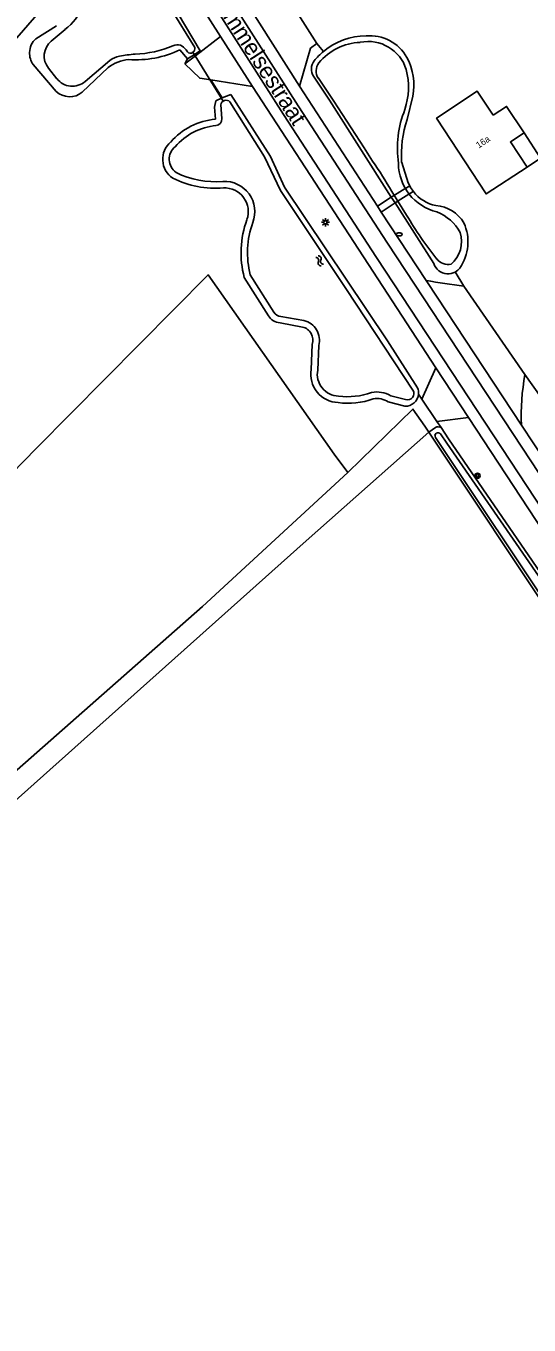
# Model space of a CAD drawing. Extents: x 137000 to 140001, y 403500 to 406000.
# Drawn here: x 139647.6 to 139724.5, y 403500 to 403698.8 of the extents above; entities that cross this region are included whole.
import ezdxf

# ---------------------------------------------------------------- set-up
doc = ezdxf.new("R2010")
doc.units = 0
for name, color, linetype in [('gg-afsc-erfafscheiding', 7, 'Continuous'), ('gg-anno-huisnummerreeks BGT', 7, 'Continuous'), ('gg-anno-openbare ruimte label', 7, 'Continuous'), ('gg-bbg-hoofdgebouw', 7, 'Continuous'), ('gg-bbg-luifel en loopbrug', 7, 'Continuous'), ('gg-knt-bronhoudergrens', 7, 'Continuous'), ('gg-knt-verharding', 7, 'Continuous'), ('gg-knt-verharding nz', 7, 'Continuous'), ('gg-kntw-bovenkant insteek waterloop', 7, 'Continuous'), ('gg-kntw-waterlijn', 7, 'Continuous'), ('gg-kwrk-duiker nz buis', 7, 'Continuous'), ('gg-kwrk-kunstwerk niveau 01', 7, 'Continuous'), ('gt-grn-groengrens', 7, 'Continuous'), ('gt-grn-vlakafsluiter', 7, 'Continuous'), ('gt-symb-boom', 7, 'Continuous'), ('gt-symb-brandkraan', 7, 'Continuous'), ('gt-symb-lichtmast', 7, 'Continuous'), ('gt-symb-watersymbool', 7, 'Continuous')]:
    doc.layers.add(name, color=color, linetype=linetype)

# ---------------------------------------------------------------- blocks, each defined once
blk = doc.blocks.new('gt0-BR')
at = {"layer": 'gt-symb-brandkraan'}
for centre, radius, start, end in [((-0.24, 0), 0.206, 107.5669, 252.4331), ((0.6, -2.66), 3, 106.892, 107.5669), ((0, -0.69), 0.938, 73.108, 106.892), ((-0.6, -2.66), 3, 72.4331, 73.108), ((0.24, 0), 0.206, 287.567, 72.4331), ((0.6, 2.66), 3, 252.4331, 253.108), ((0, 0.69), 0.938, 253.108, 286.8921), ((-0.6, 2.66), 3, 286.8921, 287.567)]:
    blk.add_arc(centre, radius, start, end, dxfattribs=at)
blk = doc.blocks.new('gt0-WA')
at = {"layer": 'gt-symb-watersymbool'}
for centre, start, end in [((-0.32, 0.02), 28.0725, 151.9275), ((0.43, 0.42), 208.0725, 331.9275), ((-0.32, -0.43), 28.0725, 151.9275), ((0.43, -0.03), 208.0725, 331.9275)]:
    blk.add_arc(centre, 0.425, start, end, dxfattribs=at)
blk = doc.blocks.new('gt0-LMAST')
at = {"layer": 'gt-symb-lichtmast'}
for p, q in [((-0.18, 0.17), (-0.45, 0.44)), ((-0.01, 0.25), (-0.01, 0.62)), ((0.17, 0.17), (0.44, 0.44)), ((-0.26, 0), (-0.63, 0)), ((-0.18, -0.18), (-0.45, -0.45)), ((-0.01, -0.25), (-0.01, -0.63)), ((0.44, -0.45), (0.17, -0.18)), ((0.24, 0), (0.62, 0))]:
    blk.add_line(p, q, dxfattribs=at)
blk.add_circle((-0.01, 0), 0.25, dxfattribs=at)
blk = doc.blocks.new('gt0-BOOM')
at = {"layer": 'gt-symb-boom'}
for radius in [0.4, 0.2]:
    blk.add_circle((0, 0), radius, dxfattribs=at)

msp = doc.modelspace()

# ---------------------------------------------------------------- linework, layer by layer
at = {"layer": 'gg-afsc-erfafscheiding'}
for p, q in [((139707.62, 403642.45), (139708.15, 403641.67)), ((139710.45, 403638.26), (139711.08, 403637.33))]:
    msp.add_line(p, q, dxfattribs=at)
msp.add_lwpolyline([(139614.8, 403661.28), (139643.81, 403694.25), (139656.94, 403709.43)], dxfattribs=at)
at = {"layer": 'gg-bbg-hoofdgebouw'}
for points in [[(139724.24, 403677.18), (139717.98, 403673.09), (139710.39, 403684.69), (139716.63, 403688.8), (139719.05, 403685.12)], [(139723.78, 403682.42), (139721.12, 403686.48), (139719.05, 403685.12)], [(139724.24, 403677.18), (139721.7, 403681.05), (139723.78, 403682.42)]]:
    msp.add_lwpolyline(points, dxfattribs=at)
at = {"layer": 'gg-bbg-luifel en loopbrug'}
msp.add_lwpolyline([(139724.24, 403677.18), (139726.32, 403678.55), (139723.78, 403682.42)], dxfattribs=at)
at = {"layer": 'gg-knt-bronhoudergrens'}
msp.add_line((139710.22, 403637.36), (139709.22, 403636.65), dxfattribs=at)
for points in [[(139696.82, 403630.48), (139694.73, 403633.24), (139675.44, 403660.73), (139649.18, 403634.19), (139617.03, 403601.2), (139533.05, 403516.15)], [(139696.82, 403630.48), (139706.78, 403640.17), (139708.61, 403637.57)], [(139696.82, 403630.48), (139674.6, 403609.96), (139617.84, 403559.95), (139598.66, 403541.96), (139599.32, 403538.78), (139622.47, 403559.29), (139690.47, 403620.01), (139709.22, 403636.65)]]:
    msp.add_lwpolyline(points, dxfattribs=at)
at = {"layer": 'gg-knt-verharding'}
for p, q in [((139660.98, 403723.06), (139677.33, 403697.18)), ((139692.1, 403696.1), (139687.81, 403702.87)), ((139681.26, 403702.41), (139689.42, 403689.6)), ((139677.33, 403697.18), (139673.5, 403694.24)), ((139677.33, 403697.18), (139682.23, 403689.51)), ((139673.5, 403694.24), (139671.89, 403693)), ((139675.85, 403690.54), (139682.23, 403689.51)), ((139682.23, 403689.51), (139710.29, 403646.46)), ((139701.34, 403671.21), (139689.42, 403689.6)), ((139701.34, 403671.21), (139703.47, 403672.61)), ((139701.94, 403670.3), (139701.34, 403671.21)), ((139701.94, 403670.3), (139704.04, 403671.72)), ((139708.79, 403659.85), (139701.94, 403670.3)), ((139723.92, 403645.43), (139714.56, 403658.99)), ((139710.29, 403646.46), (139708.15, 403641.67)), ((139715.26, 403638.85), (139710.29, 403646.46)), ((139710.45, 403638.26), (139708.15, 403641.67)), ((139715.26, 403638.85), (139710.45, 403638.26)), ((139715.26, 403638.85), (139783.75, 403534.79)), ((139742.1, 403609.27), (139723.38, 403637.68))]:
    msp.add_line(p, q, dxfattribs=at)
for points in [[(139689.42, 403689.6), (139691.09, 403695.39), (139692.1, 403696.1)], [(139671.89, 403693), (139674.17, 403690.8), (139675.85, 403690.54)]]:
    msp.add_lwpolyline(points, dxfattribs=at)
for centre, radius, start, end in [((139725.2, 403750.47), 92.09, 259.7351, 263.3693), ((139756.63, 403639.28), 33.28, 169.3419, 182.7454)]:
    msp.add_arc(centre, radius, start, end, dxfattribs=at)
at = {"layer": 'gg-knt-verharding nz'}
for p in [(139708.79, 403659.85), (139723.38, 403637.68)]:
    msp.add_line(p, (139708.99, 403659.54), dxfattribs=at)
for points in [[(139568.03, 403889.64), (139571.85, 403881.88), (139575.08, 403875.25), (139577.18, 403870.82), (139579.94, 403865.74), (139593.13, 403843.22), (139606.51, 403820.75), (139634.96, 403773.42), (139647.99, 403751.99), (139661.28, 403730.67), (139675.19, 403708.59), (139689.23, 403686.58), (139702.91, 403665.56), (139731.61, 403621.93), (139759.26, 403580.01), (139787.35, 403537.2), (139801.42, 403515.21), (139811.03, 403500)], [(139562.49, 403886.42), (139566.67, 403880.85), (139571.89, 403873.33), (139574.49, 403869.35), (139577.61, 403864.3), (139590.95, 403841.87), (139604.28, 403819.39), (139617.16, 403797.87), (139632.68, 403772.16), (139646.25, 403749.84), (139659.52, 403728.52), (139672.94, 403707.28), (139686.99, 403685.26), (139701.23, 403663.38), (139729.36, 403620.55), (139757.47, 403577.82), (139785.09, 403535.88), (139798.6, 403514.72), (139807.89, 403500)]]:
    msp.add_lwpolyline(points, dxfattribs=at)
at = {"layer": 'gg-kntw-bovenkant insteek waterloop'}
for p, q in [((139649.07, 403696.84), (139652.26, 403698.79)), ((139672.28, 403693.75), (139671.11, 403695.14)), ((139652.21, 403688.78), (139648.68, 403692.88)), ((139673.38, 403694.43), (139672.28, 403693.75)), ((139660.17, 403692.42), (139656.2, 403688.66)), ((139677.59, 403687.79), (139676.63, 403687.31)), ((139678.93, 403688.29), (139677.59, 403687.79)), ((139705.89, 403684.49), (139706.77, 403688.04)), ((139704.04, 403671.72), (139709.98, 403662.45)), ((139680.98, 403660.3), (139684.67, 403654.45)), ((139686.46, 403653.35), (139689.89, 403652.72)), ((139691.38, 403650.07), (139691.21, 403646.21)), ((139702.99, 403641.27), (139705.55, 403640.6)), ((139708.61, 403637.57), (139709.22, 403636.65)), ((139709.22, 403636.65), (139779.1, 403531.54))]:
    msp.add_line(p, q, dxfattribs=at)
for points in [[(139659.59, 403716.18), (139659.76, 403716.4), (139659.93, 403716.49), (139660.11, 403716.54), (139660.31, 403716.56), (139660.5, 403716.54), (139660.68, 403716.49), (139660.86, 403716.4), (139661.01, 403716.28), (139661.14, 403716.13), (139666.24, 403708.48), (139674.25, 403694.96), (139673.38, 403694.43)], [(139703.47, 403672.61), (139694.01, 403687.42), (139691.58, 403691.09)], [(139676.56, 403684.54), (139676.4, 403686.35), (139676.63, 403687.31)], [(139678.93, 403688.29), (139685, 403678.79), (139687.15, 403674.13), (139702.89, 403650.59), (139707.48, 403643.4)], [(139705.06, 403677.88), (139706.06, 403674.8), (139706.29, 403674.31)], [(139779.42, 403531.72), (139780.4, 403532.31), (139750.48, 403578.19), (139732.69, 403605.83), (139712.24, 403635.61), (139711.08, 403637.33)]]:
    msp.add_lwpolyline(points, dxfattribs=at)
for centre, radius, start, end in [((139651.13, 403694.64), 3.01, 133.1553, 177.8533), ((139699.71, 403686.95), 10.33, 90.5775, 129.8052), ((139700.18, 403690.79), 6.51, 29.3463, 95.0792), ((139651.13, 403694.64), 3.01, 177.8652, 215.7854), ((139664.36, 403709.36), 15.75, 266.0094, 295.3982), ((139699.77, 403686.88), 10.42, 129.8156, 140.8706), ((139663.71, 403688.03), 5.64, 94.6035, 128.8584), ((139693.24, 403692.19), 2, 140.929, 213.6046), ((139693.97, 403691.89), 2, 141.3117, 213.8922), ((139697.74, 403689.7), 9.18, 349.6017, 27.808), ((139654.27, 403690.98), 3.02, 227.013, 309.5914), ((139677.53, 403674.21), 10.37, 95.3329, 138.8764), ((139721.96, 403679.11), 16.95, 161.5084, 184.1775), ((139671.96, 403678.39), 3.47, 130.3041, 236.3572), ((139676.63, 403688.84), 14.88, 243.7038, 274.4511), ((139677.94, 403670.36), 3.65, 340.6087, 92.5172), ((139711.39, 403676.92), 5.72, 217.3976, 259.0127), ((139709.92, 403665.92), 5.4, 30.4394, 85.9918), ((139695.05, 403664.08), 14.57, 159.6737, 195.0289), ((139708.2, 403665.75), 7, 325.1424, 24.4553), ((139712.1, 403663.09), 2.22, 196.918, 266.8661), ((139712.19, 403663.03), 2.17, 264.4247, 299.0321), ((139712.41, 403662.79), 1.85, 296.6018, 325.8508), ((139686.66, 403655.68), 2.34, 211.8434, 265.0097), ((139689.42, 403650.71), 2.06, 341.8999, 76.8279), ((139695.5, 403645.5), 4.35, 170.5464, 267.7086), ((139705.6, 403642.63), 2.03, 354.9718, 22.3846), ((139696.8, 403652.92), 11.86, 262.8472, 289.2704), ((139701.29, 403638.67), 3.11, 56.7784, 100.6404), ((139705.61, 403642.63), 2.03, 268.4876, 354.9098), ((139710.62, 403636.56), 0.896, 59.0408, 116.4312)]:
    msp.add_arc(centre, radius, start, end, dxfattribs=at)
at = {"layer": 'gg-kntw-waterlijn'}
for p, q in [((139653.55, 403698.26), (139651.44, 403696.48)), ((139672.08, 403695.12), (139672.28, 403694.81)), ((139660.41, 403693.5), (139656.61, 403690.28)), ((139651.03, 403692.32), (139652.32, 403690.69)), ((139677.56, 403684.62), (139677.37, 403686.74)), ((139705.82, 403669.84), (139703.56, 403673.48)), ((139685.52, 403654.98), (139681.9, 403660.71)), ((139690.09, 403653.7), (139686.58, 403654.34)), ((139692.21, 403646.11), (139692.37, 403649.9)), ((139705.64, 403641.61), (139703.4, 403642.2)), ((139778.95, 403532.67), (139710.23, 403635.83))]:
    msp.add_line(p, q, dxfattribs=at)
for points in [[(139673.4, 403695.51), (139665.97, 403707.58), (139660.98, 403714.89)], [(139700.6, 403678.12), (139699.33, 403680.16), (139694.66, 403687.28), (139692.31, 403690.78)], [(139678.79, 403687.2), (139684.06, 403678.75), (139686.52, 403673.61), (139696.64, 403658.47), (139706.79, 403643.06)], [(139710.99, 403636.35), (139711.96, 403634.96), (139732.28, 403605.56), (139750.06, 403577.92), (139779.37, 403532.97)]]:
    msp.add_lwpolyline(points, dxfattribs=at)
for centre, radius, start, end in [((139649.44, 403704.08), 7.12, 305.2369, 341.6417), ((139653.37, 403694.19), 3, 130.1266, 218.6047), ((139663.9, 403710.28), 15.79, 271.3642, 292.9994), ((139670.74, 403694.36), 1.54, 29.6826, 115.8794), ((139672.74, 403695.31), 0.685, 226.8564, 16.9431), ((139698.95, 403687.9), 8.38, 91.6076, 141.3187), ((139699.93, 403690.3), 6.11, 17.2795, 101.5035), ((139662.35, 403691.22), 2.99, 99.0749, 130.3015), ((139668.8, 403651.25), 43.48, 95.9682, 99.1617), ((139654.67, 403692.57), 3, 218.6128, 310.2971), ((139695.11, 403689.42), 10.98, 341.8829, 14.1562), ((139678.21, 403686.56), 0.862, 47.9063, 168.5767), ((139720.41, 403680.04), 16.01, 158.1083, 188.1908), ((139677.52, 403674.21), 9.37, 95.3249, 139.3663), ((139676.56, 403684.54), 1, 275.3696, 5.092), ((139671.96, 403678.39), 2.47, 128.6641, 234.9909), ((139630.45, 403630.08), 85.02, 30.691, 34.4046), ((139712.26, 403677.81), 7.7, 180.3714, 256.3612), ((139676.63, 403688.84), 13.89, 243.9942, 274.5083), ((139677.94, 403670.36), 4.65, 339.227, 92.7389), ((139752.8, 403697.26), 54.4, 210.2717, 218.8634), ((139707.96, 403663.95), 6.85, 28.0803, 68.6927), ((139695.04, 403664.08), 13.57, 160.0669, 194.4083), ((139709.68, 403665.8), 4.53, 310.2971, 17.5832), ((139712.16, 403664.5), 2.2, 218.4148, 281.7037), ((139686.66, 403655.68), 1.34, 211.7251, 266.7438), ((139689.42, 403650.71), 3.06, 344.7237, 77.3102), ((139695.5, 403645.5), 3.35, 169.578, 268.4098), ((139705.95, 403642.55), 0.983, 251.7554, 31.2742), ((139696.8, 403652.92), 10.86, 262.6134, 289.6329), ((139701.29, 403638.67), 4.11, 59.208, 101.779), ((139710.61, 403636.09), 0.462, 34.7845, 214.692)]:
    msp.add_arc(centre, radius, start, end, dxfattribs=at)
at = {"layer": 'gg-kwrk-duiker nz buis'}
msp.add_line((139673.06, 403694.88), (139677.77, 403687.3), dxfattribs=at)
at = {"layer": 'gg-kwrk-kunstwerk niveau 01'}
for p, q in [((139704.35, 403673.14), (139703.47, 403672.61)), ((139705.18, 403673.65), (139704.35, 403673.14)), ((139706.29, 403674.31), (139705.18, 403673.65)), ((139706.84, 403673.45), (139705.76, 403672.78)), ((139703.47, 403672.61), (139704.04, 403671.72)), ((139704.04, 403671.72), (139704.91, 403672.26)), ((139704.91, 403672.26), (139705.76, 403672.78))]:
    msp.add_line(p, q, dxfattribs=at)
msp.add_arc((139711.25, 403676.88), 5.59, 207.4316, 217.965, dxfattribs=at)
at = {"layer": 'gt-grn-groengrens'}
for p, q in [((139692.1, 403696.1), (139693.1, 403694.88)), ((139671.89, 403693), (139672.28, 403693.75)), ((139714.56, 403658.99), (139713.24, 403661.14)), ((139726.38, 403641.91), (139723.92, 403645.43))]:
    msp.add_line(p, q, dxfattribs=at)
at = {"layer": 'gt-grn-vlakafsluiter'}
for p, q in [((139673.38, 403694.43), (139673.5, 403694.24)), ((139677.59, 403687.79), (139675.85, 403690.54))]:
    msp.add_line(p, q, dxfattribs=at)

# ---------------------------------------------------------------- block references
at = {"layer": 'gt-symb-boom'}
msp.add_blockref('gt0-BOOM', (139716.66, 403629.96), dxfattribs=at)
at = {"layer": 'gt-symb-brandkraan'}
msp.add_blockref('gt0-BR', (139704.68, 403666.9), dxfattribs=at)
at = {"layer": 'gt-symb-lichtmast'}
msp.add_blockref('gt0-LMAST', (139693.41, 403668.74), dxfattribs=at)
at = {"layer": 'gt-symb-watersymbool', "rotation": 123.78542795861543}
msp.add_blockref('gt0-WA', (139692.53, 403662.8), dxfattribs=at)

# ---------------------------------------------------------------- texts
at = {"layer": 'gg-anno-huisnummerreeks BGT'}
msp.add_text('16a', height=1, rotation=33.2, dxfattribs=at).set_placement((139716.83, 403680.02))
at = {"layer": 'gg-anno-openbare ruimte label'}
msp.add_text('Gommelsestraat', height=2.5, rotation=302.9, dxfattribs=at).set_placement((139675.23, 403703.96))

doc.saveas('drawing.dxf')
